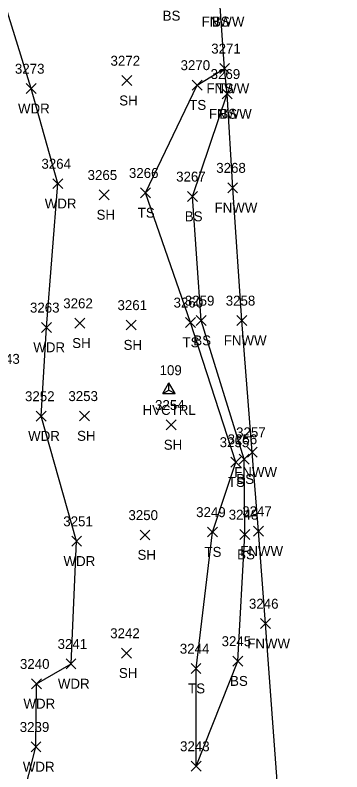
# Model space of a CAD drawing. Extents: x 1650221 to 1650634, y 244606 to 249996.
# Drawn here: x 1650480.3 to 1650546, y 245823.9 to 245976.3 of the extents above; entities that cross this region are included whole.
import ezdxf

# ---------------------------------------------------------------- set-up
doc = ezdxf.new("R2010")
doc.units = 0
for name, color, linetype in [('C_A', 7, 'Continuous'), ('C_I', 7, 'Continuous'), ('CPSM', 7, 'Continuous'), ('L_A', 7, 'Continuous'), ('L_I', 7, 'Continuous'), ('L_TIC', 7, 'Continuous'), ('LAWA', 7, 'Continuous'), ('LELB', 7, 'Continuous'), ('LFNC', 7, 'Continuous'), ('LSOGP', 7, 'Continuous')]:
    doc.layers.add(name, color=color, linetype=linetype)

msp = doc.modelspace()

# ---------------------------------------------------------------- linework, layer by layer
at = {"layer": 'CPSM'}
for p, q in [((1650509.99, 245900.04), (1650511.24, 245902.2)), ((1650512.49, 245900.04), (1650511.24, 245902.2)), ((1650511.24, 245900.76), (1650511.24, 245902.2)), ((1650509.99, 245900.04), (1650511.24, 245900.76)), ((1650509.99, 245900.04), (1650512.49, 245900.04)), ((1650511.24, 245900.76), (1650511.24, 245900.76)), ((1650511.24, 245900.76), (1650512.49, 245900.04))]:
    msp.add_line(p, q, dxfattribs=at)
at = {"layer": 'L_TIC'}
for points in [[(1650521.45, 245964.53), (1650523.45, 245966.53)], [(1650523.45, 245964.53), (1650521.45, 245966.53)], [(1650521.45, 245964.53), (1650523.45, 245966.53)], [(1650523.45, 245964.53), (1650521.45, 245966.53)], [(1650501.75, 245962.08), (1650503.75, 245964.08)], [(1650503.75, 245962.08), (1650501.75, 245964.08)], [(1650482.51, 245960.47), (1650484.51, 245962.47)], [(1650484.51, 245960.47), (1650482.51, 245962.47)], [(1650515.93, 245961.19), (1650517.93, 245963.19)], [(1650517.93, 245961.19), (1650515.93, 245963.19)], [(1650521.94, 245959.4), (1650523.94, 245961.4)], [(1650523.94, 245959.4), (1650521.94, 245961.4)], [(1650521.94, 245959.4), (1650523.94, 245961.4)], [(1650523.94, 245959.4), (1650521.94, 245961.4)], [(1650487.88, 245941.33), (1650489.88, 245943.33)], [(1650489.88, 245941.33), (1650487.88, 245943.33)], [(1650523.07, 245940.51), (1650525.07, 245942.51)], [(1650525.07, 245940.51), (1650523.07, 245942.51)], [(1650497.19, 245939.06), (1650499.19, 245941.06)], [(1650499.19, 245939.06), (1650497.19, 245941.06)], [(1650505.55, 245939.48), (1650507.55, 245941.48)], [(1650507.55, 245939.48), (1650505.55, 245941.48)], [(1650515, 245938.75), (1650517, 245940.75)], [(1650517, 245938.75), (1650515, 245940.75)], [(1650492.29, 245913.23), (1650494.29, 245915.23)], [(1650494.29, 245913.23), (1650492.29, 245915.23)], [(1650502.63, 245912.86), (1650504.63, 245914.86)], [(1650504.63, 245912.86), (1650502.63, 245914.86)], [(1650514.56, 245913.38), (1650516.56, 245915.38)], [(1650516.56, 245913.38), (1650514.56, 245915.38)], [(1650516.71, 245913.76), (1650518.71, 245915.76)], [(1650518.71, 245913.76), (1650516.71, 245915.76)], [(1650524.93, 245913.77), (1650526.93, 245915.77)], [(1650526.93, 245913.77), (1650524.93, 245915.77)], [(1650485.59, 245912.37), (1650487.59, 245914.37)], [(1650487.59, 245912.37), (1650485.59, 245914.37)], [(1650484.54, 245894.52), (1650486.54, 245896.52)], [(1650486.54, 245894.52), (1650484.54, 245896.52)], [(1650493.27, 245894.54), (1650495.27, 245896.54)], [(1650495.27, 245894.54), (1650493.27, 245896.54)], [(1650510.71, 245892.74), (1650512.71, 245894.74)], [(1650512.71, 245892.74), (1650510.71, 245894.74)], [(1650527.02, 245887.24), (1650529.02, 245889.24)], [(1650529.02, 245887.24), (1650527.02, 245889.24)], [(1650523.71, 245885.26), (1650525.71, 245887.26)], [(1650525.71, 245885.26), (1650523.71, 245887.26)], [(1650525.37, 245885.85), (1650527.37, 245887.85)], [(1650527.37, 245885.85), (1650525.37, 245887.85)], [(1650505.43, 245870.57), (1650507.43, 245872.57)], [(1650507.43, 245870.57), (1650505.43, 245872.57)], [(1650518.98, 245871.17), (1650520.98, 245873.17)], [(1650520.98, 245871.17), (1650518.98, 245873.17)], [(1650525.53, 245870.66), (1650527.53, 245872.66)], [(1650527.53, 245870.66), (1650525.53, 245872.66)], [(1650528.25, 245871.35), (1650530.25, 245873.35)], [(1650530.25, 245871.35), (1650528.25, 245873.35)], [(1650491.67, 245869.32), (1650493.67, 245871.32)], [(1650493.67, 245869.32), (1650491.67, 245871.32)], [(1650529.66, 245852.72), (1650531.66, 245854.72)], [(1650531.66, 245852.72), (1650529.66, 245854.72)], [(1650501.68, 245846.78), (1650503.68, 245848.78)], [(1650503.68, 245846.78), (1650501.68, 245848.78)], [(1650490.54, 245844.62), (1650492.54, 245846.62)], [(1650492.54, 245844.62), (1650490.54, 245846.62)], [(1650524.1, 245845.18), (1650526.1, 245847.18)], [(1650526.1, 245845.18), (1650524.1, 245847.18)], [(1650515.69, 245843.67), (1650517.69, 245845.67)], [(1650517.69, 245843.67), (1650515.69, 245845.67)], [(1650483.6, 245840.6), (1650485.6, 245842.6)], [(1650485.6, 245840.6), (1650483.6, 245842.6)], [(1650483.49, 245827.9), (1650485.49, 245829.9)], [(1650485.49, 245827.9), (1650483.49, 245829.9)], [(1650515.74, 245824.02), (1650517.74, 245826.02)], [(1650517.74, 245824.02), (1650515.74, 245826.02)], [(1650515.74, 245824.02), (1650517.74, 245826.02)], [(1650517.74, 245824.02), (1650515.74, 245826.02)]]:
    msp.add_lwpolyline(points, dxfattribs=at)
at = {"layer": 'LAWA'}
msp.add_lwpolyline([(1650496.59, 245647.08), (1650490.62, 245662.71), (1650491.66, 245676.81), (1650494.11, 245688.94), (1650496.41, 245712.71), (1650496.35, 245743.56), (1650485.42, 245749.48), (1650477.6, 245752.97), (1650479.59, 245781.46), (1650478.59, 245799.8), (1650480.21, 245812.21), (1650484.49, 245828.9), (1650484.6, 245841.6), (1650491.54, 245845.62), (1650492.67, 245870.32), (1650485.54, 245895.52), (1650486.59, 245913.37), (1650488.88, 245942.33), (1650483.51, 245961.47), (1650475.64, 245986.69)], dxfattribs=at)
at = {"layer": 'LELB'}
for points in [[(1650516.74, 245825.02), (1650516.69, 245844.67), (1650519.98, 245872.17), (1650524.71, 245886.26), (1650515.56, 245914.38), (1650506.55, 245940.48), (1650516.93, 245962.19), (1650522.45, 245965.53)], [(1650516.74, 245825.02), (1650525.1, 245846.18), (1650526.53, 245871.66), (1650526.37, 245886.85), (1650517.71, 245914.76), (1650516, 245939.75), (1650522.94, 245960.4)]]:
    msp.add_lwpolyline(points, dxfattribs=at)
at = {"layer": 'LFNC'}
msp.add_lwpolyline([(1650546.03, 245639.46), (1650543.33, 245680.57), (1650541.25, 245706.23), (1650538.76, 245743.38), (1650537.2, 245769.33), (1650535.19, 245793.78), (1650533.98, 245796.82), (1650533.26, 245818.39), (1650530.66, 245853.72), (1650529.25, 245872.35), (1650528.02, 245888.24), (1650525.93, 245914.77), (1650524.07, 245941.51), (1650522.94, 245960.4), (1650522.45, 245965.53), (1650521.47, 245978.98)], dxfattribs=at)
at = {"layer": 'LSOGP'}
msp.add_lwpolyline([(1650546.03, 245639.46), (1650543.33, 245680.57), (1650541.25, 245706.23), (1650538.76, 245743.38), (1650537.2, 245769.33), (1650535.19, 245793.78), (1650533.98, 245796.82), (1650533.26, 245818.39), (1650530.66, 245853.72), (1650529.25, 245872.35), (1650528.02, 245888.24), (1650525.93, 245914.77), (1650524.07, 245941.51), (1650522.94, 245960.4), (1650522.45, 245965.53), (1650521.47, 245978.98)], dxfattribs=at)

# ---------------------------------------------------------------- texts
at = {"layer": 'C_A'}
msp.add_text('HVCTRL', height=2, dxfattribs=at).set_placement((1650505.94, 245895.76))
at = {"layer": 'C_I'}
msp.add_text('109', height=2, dxfattribs=at).set_placement((1650509.36, 245903.76))
at = {"layer": 'L_A'}
for s, p in [('BS', (1650509.98, 245975.16)), ('FNWW', (1650517.81, 245973.98)), ('BS', (1650519.91, 245973.98)), ('FNWW', (1650518.79, 245960.53)), ('TS', (1650520.85, 245960.53)), ('SH', (1650501.24, 245958.08)), ('TS', (1650515.33, 245957.19)), ('WDR', (1650480.87, 245956.47)), ('FNWW', (1650519.29, 245955.4)), ('BS', (1650521.38, 245955.4)), ('WDR', (1650486.25, 245937.33)), ('TS', (1650504.96, 245935.48)), ('FNWW', (1650520.42, 245936.51)), ('SH', (1650496.68, 245935.06)), ('BS', (1650514.44, 245934.75)), ('BS', (1650516.15, 245909.76)), ('FNWW', (1650522.28, 245909.77)), ('WDR', (1650483.95, 245908.37)), ('SH', (1650491.78, 245909.23)), ('SH', (1650502.12, 245908.86)), ('TS', (1650513.97, 245909.38)), ('WDR', (1650482.91, 245890.52)), ('SH', (1650492.76, 245890.54)), ('SH', (1650510.2, 245888.74)), ('FNWW', (1650524.37, 245883.24)), ('TS', (1650523.12, 245881.26)), ('BS', (1650524.81, 245881.85)), ('TS', (1650518.39, 245867.17)), ('FNWW', (1650525.59, 245867.35)), ('WDR', (1650490.03, 245865.32)), ('SH', (1650504.92, 245866.57)), ('BS', (1650524.97, 245866.66)), ('FNWW', (1650527, 245848.72)), ('SH', (1650501.17, 245842.78)), ('BS', (1650523.54, 245841.18)), ('WDR', (1650488.9, 245840.62)), ('TS', (1650515.1, 245839.67)), ('WDR', (1650481.97, 245836.6)), ('WDR', (1650481.85, 245823.9))]:
    msp.add_text(s, height=2, dxfattribs=at).set_placement(p)
at = {"layer": 'L_I'}
for s, p in [('3271', (1650519.75, 245968.53)), ('3271', (1650519.75, 245968.53)), ('3272', (1650499.49, 245966.08)), ('3273', (1650480.25, 245964.47)), ('3270', (1650513.58, 245965.19)), ('3269', (1650519.63, 245963.4)), ('3269', (1650519.63, 245963.4)), ('3264', (1650485.58, 245945.33)), ('3265', (1650494.88, 245943.06)), ('3266', (1650503.19, 245943.48)), ('3268', (1650520.76, 245944.51)), ('3267', (1650512.69, 245942.75)), ('3262', (1650489.98, 245917.23)), ('3260', (1650512.17, 245917.38)), ('3259', (1650514.44, 245917.76)), ('3258', (1650522.67, 245917.77)), ('3263', (1650483.28, 245916.37)), ('3261', (1650500.89, 245916.86)), ('2243', (1650475.28, 245906.04)), ('3252', (1650482.28, 245898.52)), ('3253', (1650491.01, 245898.54)), ('3254', (1650508.45, 245896.74)), ('3257', (1650524.76, 245891.24)), ('3256', (1650523.05, 245889.85)), ('3255', (1650521.45, 245889.26)), ('3250', (1650503.09, 245874.57)), ('3249', (1650516.71, 245875.17)), ('3248', (1650523.27, 245874.66)), ('3247', (1650525.99, 245875.35)), ('3251', (1650489.98, 245873.32)), ('3246', (1650527.34, 245856.72)), ('3242', (1650499.42, 245850.78)), ('3241', (1650488.84, 245848.62)), ('3245', (1650521.84, 245849.18)), ('3244', (1650513.43, 245847.67)), ('3240', (1650481.26, 245844.6)), ('3239', (1650481.22, 245831.9)), ('3243', (1650513.48, 245828.02)), ('3243', (1650513.48, 245828.02))]:
    msp.add_text(s, height=2, dxfattribs=at).set_placement(p)

doc.saveas('drawing.dxf')
